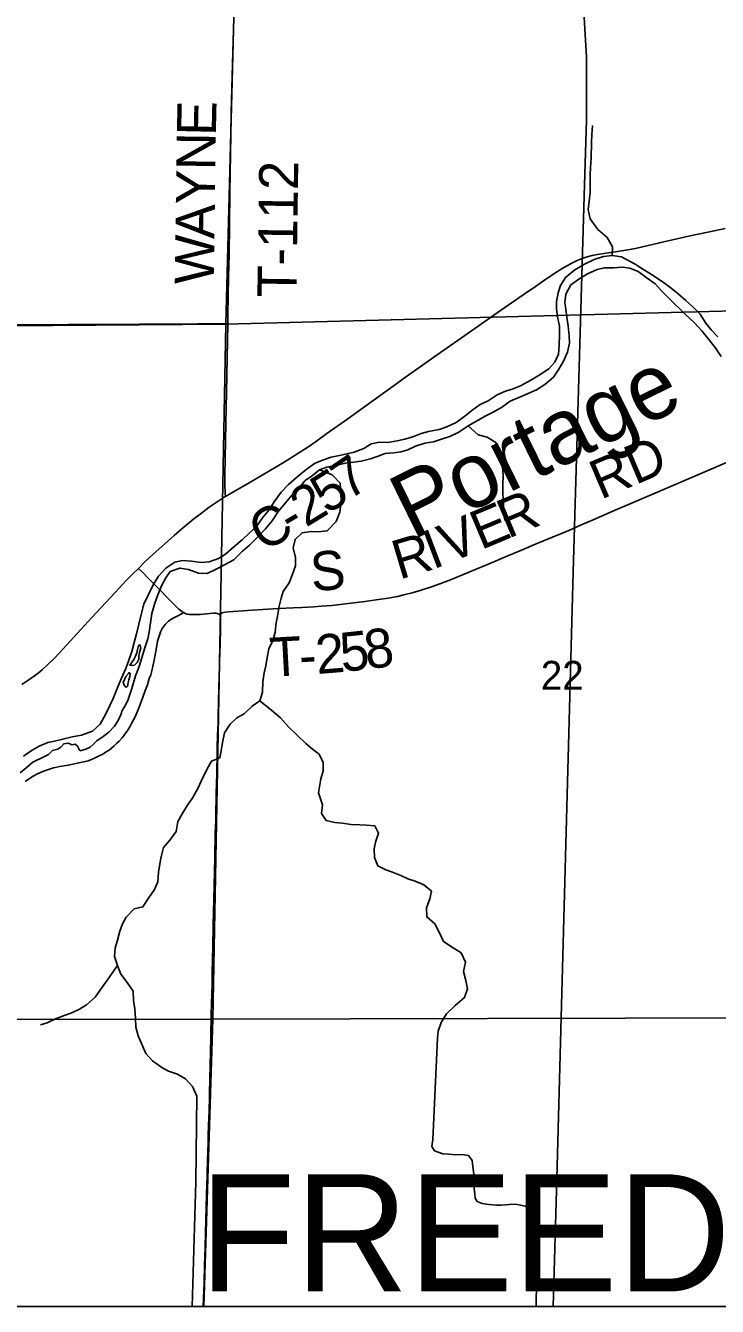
# Model space of a CAD drawing. Extents: x 0 to 34, y 0 to 22.
# Drawn here: x 3.748 to 4.754, y 14.1 to 15.963 of the extents above; entities that cross this region are included whole.
import ezdxf

# ---------------------------------------------------------------- set-up
doc = ezdxf.new("R2010")
doc.units = 0
for name, color, linetype in [('Default', 7, 'Continuous'), ('GM_X_County_Road', 7, 'Continuous'), ('GM_X_County_Road_Text', 7, 'Continuous'), ('GM_X_Major_River', 7, 'Continuous'), ('GM_X_Major_River_Text', 7, 'Continuous'), ('GM_X_Minor_River', 7, 'Continuous'), ('GM_X_Rail_Line', 7, 'Continuous'), ('GM_X_Section', 7, 'Continuous'), ('GM_X_Section_Text', 7, 'Continuous'), ('GM_X_Township_Road', 7, 'Continuous'), ('GM_X_Township_Road_Text', 7, 'Continuous'), ('GM_X_Township_Text', 7, 'Continuous'), ('SH_Cut_Line', 7, 'Continuous'), ('SH_Data', 7, 'Continuous')]:
    doc.layers.add(name, color=color, linetype=linetype)

msp = doc.modelspace()

# ---------------------------------------------------------------- linework, layer by layer
at = {"layer": 'Default'}
for points in [[(3.005, 14.1), (4.0075, 14.1), (4.0206, 14.5179), (3.0117, 14.5162)], [(4.0075, 14.1), (5.0106, 14.1), (5.0199, 14.516), (5.0199, 14.5201), (4.0206, 14.5179)]]:
    msp.add_lwpolyline(points, close=True, dxfattribs=at)
msp.add_lwpolyline([(2.1, 14.1), (7.0155, 14.1)], dxfattribs=at)
at = {"layer": 'GM_X_County_Road'}
for points in [[(4.0391, 15.2781), (4.0503, 15.2849), (4.0732, 15.298), (4.1029, 15.3151), (4.1242, 15.328), (4.144, 15.3403), (4.1571, 15.3488), (4.1712, 15.3585), (4.1863, 15.3694), (4.2167, 15.3911), (4.2395, 15.4072), (4.2862, 15.4409), (4.2975, 15.4491), (4.3418, 15.4806), (4.4018, 15.5224), (4.4387, 15.5483), (4.4514, 15.5573), (4.4732, 15.5721), (4.4899, 15.5836), (4.5014, 15.5916), (4.5181, 15.6029), (4.5272, 15.6088), (4.5352, 15.6135), (4.5434, 15.6179), (4.5504, 15.6211), (4.5576, 15.6239), (4.5649, 15.6264), (4.5724, 15.6284), (4.5799, 15.6301), (4.5891, 15.6316), (4.606, 15.6337), (4.6122, 15.6346), (4.6214, 15.6361), (4.6352, 15.6389), (4.67, 15.6471), (4.7125, 15.6564), (4.7429, 15.663), (4.7657, 15.668)], [(3.9122, 15.1734), (3.9216, 15.183), (3.933, 15.1935), (3.9644, 15.2213), (3.9761, 15.2315), (3.9929, 15.2453), (4.0039, 15.2539), (4.0151, 15.2622), (4.0253, 15.2693), (4.0371, 15.2769), (4.0391, 15.2781)], [(3.7427, 15.0044), (3.7516, 15.0102), (3.7612, 15.017), (3.7665, 15.0212), (3.7722, 15.0259), (3.7804, 15.0335), (3.7902, 15.043), (3.803, 15.0565), (3.8285, 15.0846), (3.8446, 15.1019), (3.8649, 15.1238), (3.8785, 15.1383), (3.8946, 15.1556), (3.9041, 15.1655), (3.9122, 15.1734)], [(3.9781, 15.109), (3.9775, 15.1093), (3.9748, 15.111), (3.9712, 15.1141), (3.9634, 15.1217), (3.9568, 15.1283), (3.9396, 15.146), (3.9363, 15.1493), (3.9319, 15.1536), (3.9287, 15.1569), (3.9243, 15.1612), (3.9189, 15.1667), (3.9122, 15.1734)], [(4.0306, 15.106), (4.0289, 15.1075), (4.0264, 15.108), (4.025, 15.1082), (4.022, 15.1083), (4.0159, 15.1079), (4.0021, 15.1065), (3.9959, 15.1061), (3.9896, 15.1061), (3.9864, 15.1063), (3.9833, 15.1068), (3.9803, 15.1079), (3.9781, 15.109)], [(4.0066, 14.1), (4.0078, 14.1341), (4.0085, 14.1605), (4.0088, 14.1714), (4.0093, 14.1869), (4.0104, 14.2257), (4.0113, 14.2615), (4.0117, 14.277), (4.0121, 14.291), (4.0128, 14.3158), (4.013, 14.3221), (4.0136, 14.3407), (4.0139, 14.35), (4.0143, 14.3624), (4.0149, 14.3842), (4.0154, 14.4044), (4.0156, 14.4106), (4.0161, 14.4308), (4.0169, 14.4696), (4.0174, 14.4914), (4.0182, 14.5256), (4.0193, 14.5691), (4.0196, 14.5831), (4.0201, 14.6064), (4.0204, 14.6219), (4.0211, 14.6546), (4.0219, 14.6919), (4.0232, 14.7525), (4.0241, 14.7882), (4.0246, 14.8069), (4.0248, 14.8146), (4.025, 14.8255), (4.0251, 14.8317), (4.0255, 14.8457), (4.0262, 14.8752), (4.0268, 14.9063), (4.0269, 14.9125), (4.0274, 14.9311), (4.028, 14.9482), (4.0283, 14.9591), (4.0288, 14.9793), (4.0294, 14.9995), (4.0298, 15.0166), (4.0301, 15.0305), (4.0303, 15.0399), (4.0305, 15.0492), (4.031, 15.0649), (4.0315, 15.0825), (4.0315, 15.0892), (4.0315, 15.1012), (4.0313, 15.1039), (4.0306, 15.106)]]:
    msp.add_lwpolyline(points, dxfattribs=at)
at = {"layer": 'GM_X_Major_River'}
for p, q in [((3.9126, 15.0412), (3.9127, 15.045)), ((3.8938, 15.0159), (3.891, 15.0095))]:
    msp.add_line(p, q, dxfattribs=at)
for points in [[(4.5612, 15.6161), (4.5469, 15.6077), (4.5334, 15.5966), (4.5263, 15.5847), (4.5226, 15.5741), (4.5204, 15.5609), (4.5202, 15.5514), (4.5218, 15.5392), (4.5245, 15.5255), (4.5249, 15.5126), (4.5242, 15.4982), (4.5231, 15.4849), (4.5179, 15.4733), (4.5093, 15.4636), (4.4966, 15.4552), (4.4839, 15.4476), (4.4678, 15.4388), (4.4559, 15.4342), (4.4464, 15.431), (4.4341, 15.4256), (4.421, 15.4172), (4.4095, 15.4118), (4.3991, 15.4044), (4.3868, 15.3949), (4.3744, 15.3857), (4.361, 15.3792), (4.3496, 15.3753), (4.3343, 15.3726), (4.3233, 15.3698), (4.3114, 15.3648), (4.2996, 15.3613), (4.2886, 15.3589), (4.2749, 15.3566), (4.2628, 15.3569), (4.251, 15.3545), (4.2402, 15.3479), (4.226, 15.3422), (4.2047, 15.3374), (4.1925, 15.3351), (4.1799, 15.3308), (4.1685, 15.3261), (4.1557, 15.3166), (4.1422, 15.3055), (4.1306, 15.2956), (4.1197, 15.2841), (4.1095, 15.2703), (4.1024, 15.2587), (4.0927, 15.2468), (4.084, 15.2341), (4.0739, 15.2252), (4.0631, 15.2148), (4.0511, 15.2049), (4.0387, 15.1942), (4.0287, 15.188), (4.0153, 15.183), (4.004, 15.1821), (3.9896, 15.184), (3.9764, 15.1847), (3.9653, 15.1823), (3.9522, 15.1735), (3.9414, 15.162), (3.9335, 15.1493), (3.9263, 15.1343), (3.9203, 15.1215), (3.9161, 15.1061), (3.9093, 15.0784), (3.9062, 15.0655), (3.9027, 15.0525), (3.8978, 15.0382), (3.8937, 15.0277), (3.8873, 15.0126), (3.8813, 14.9987), (3.8756, 14.9841), (3.8708, 14.9739), (3.8644, 14.9608), (3.8565, 14.947), (3.8453, 14.9366), (3.8296, 14.9309), (3.8159, 14.9282), (3.8022, 14.9251), (3.79, 14.922), (3.7805, 14.9203), (3.7679, 14.9149), (3.7575, 14.9091), (3.7451, 14.9003)], [(3.9025, 14.9986), (3.9082, 15.0171), (3.9131, 15.0306), (3.9172, 15.0434), (3.9213, 15.0566), (3.9258, 15.0709), (3.928, 15.0807), (3.9317, 15.108), (3.9362, 15.1226), (3.9407, 15.1347), (3.9459, 15.1478), (3.9523, 15.1598), (3.9585, 15.1688), (3.9727, 15.1738), (3.9851, 15.1716), (3.9998, 15.1663), (4.0123, 15.166), (4.0245, 15.1717), (4.0376, 15.1786), (4.051, 15.1859), (4.0638, 15.1985), (4.0739, 15.2074), (4.0863, 15.22), (4.0972, 15.2307), (4.1069, 15.2426), (4.116, 15.2564), (4.1261, 15.2687), (4.1357, 15.2806), (4.1456, 15.2903), (4.1546, 15.3011), (4.1654, 15.3084), (4.1758, 15.3169), (4.1861, 15.3208), (4.1991, 15.3231), (4.2135, 15.3266), (4.2253, 15.3278), (4.2363, 15.3291), (4.25, 15.3325), (4.2611, 15.3368), (4.2711, 15.3404), (4.2836, 15.3416), (4.2938, 15.3429), (4.3042, 15.346), (4.3153, 15.3514), (4.329, 15.3557), (4.3416, 15.3576), (4.353, 15.3612), (4.3652, 15.3654), (4.3783, 15.3716), (4.3921, 15.3807), (4.4175, 15.3953), (4.4274, 15.4), (4.4405, 15.4076), (4.4532, 15.4164), (4.4655, 15.4218), (4.4792, 15.4276), (4.4911, 15.433), (4.5034, 15.441), (4.5162, 15.4517), (4.5237, 15.4633), (4.5304, 15.4749), (4.5364, 15.488), (4.5394, 15.5012), (4.5389, 15.5115), (4.5373, 15.5263), (4.5354, 15.5382), (4.5338, 15.5503), (4.5325, 15.5599), (4.5339, 15.5723), (4.5411, 15.5858), (4.553, 15.5939), (4.5653, 15.6016), (4.5795, 15.6081), (4.5902, 15.6105), (4.6034, 15.6105), (4.616, 15.6114), (4.6269, 15.6099), (4.6393, 15.6051), (4.6523, 15.5957), (4.6638, 15.5874), (4.673, 15.577), (4.6841, 15.5657), (4.7085, 15.5423), (4.7208, 15.531), (4.7318, 15.519)], [(4.7551, 15.5104), (4.7455, 15.5205), (4.7378, 15.5302), (4.7294, 15.5433), (4.7196, 15.5529), (4.7087, 15.5628), (4.6972, 15.5726), (4.6845, 15.5827), (4.6726, 15.5918), (4.6585, 15.6008), (4.6447, 15.6095), (4.635, 15.6158), (4.6148, 15.6266), (4.6012, 15.6284), (4.5887, 15.6272), (4.575, 15.6226), (4.5612, 15.6161)], [(4.7318, 15.519), (4.7421, 15.5062), (4.7513, 15.4946), (4.76, 15.4815)], [(3.9127, 15.045), (3.914, 15.0511), (3.9157, 15.0579), (3.9143, 15.0621), (3.9123, 15.061), (3.9111, 15.0553), (3.9098, 15.0504), (3.9082, 15.0455), (3.9054, 15.041), (3.8995, 15.0328), (3.9029, 15.032), (3.9063, 15.0327), (3.9106, 15.0367), (3.9126, 15.0412)], [(3.891, 15.0095), (3.8902, 15.008), (3.8916, 15.0034), (3.8938, 15.0007), (3.8957, 15.0014), (3.8965, 15.0018), (3.8974, 15.0075), (3.8982, 15.0112), (3.8999, 15.0161), (3.9003, 15.0199), (3.8989, 15.0218), (3.8977, 15.0204), (3.8938, 15.0159)], [(3.74, 14.8761), (3.752, 14.8857), (3.7586, 14.8913), (3.7758, 14.8996), (3.7816, 14.9025), (3.7862, 14.9077), (3.7874, 14.9084), (3.795, 14.9105), (3.7992, 14.9134), (3.8035, 14.9183), (3.8104, 14.9192), (3.8156, 14.9168), (3.8202, 14.9175), (3.8243, 14.9143), (3.8257, 14.9105), (3.8275, 14.9082), (3.8359, 14.9103), (3.842, 14.9135), (3.8474, 14.918), (3.8517, 14.9224), (3.861, 14.929), (3.8691, 14.9353), (3.8776, 14.9438), (3.882, 14.9505), (3.886, 14.9588), (3.8888, 14.9667), (3.8932, 14.9745), (3.8971, 14.9828), (3.9025, 14.9986)]]:
    msp.add_lwpolyline(points, dxfattribs=at)
at = {"layer": 'GM_X_Minor_River'}
for points in [[(4.6012, 15.6284), (4.6019, 15.6409), (4.5939, 15.6548), (4.5806, 15.6665), (4.5692, 15.6819), (4.5665, 15.6953), (4.568, 15.7074), (4.5694, 15.7199), (4.5693, 15.7313), (4.5693, 15.7461), (4.5696, 15.7563), (4.5707, 15.7703), (4.5712, 15.7931), (4.5719, 15.8041), (4.5726, 15.8177)], [(4.3921, 15.3807), (4.4062, 15.3678), (4.4193, 15.3641), (4.432, 15.3566), (4.4363, 15.347), (4.4402, 15.3336), (4.4418, 15.3211), (4.443, 15.3089), (4.4422, 15.2949), (4.4423, 15.2816), (4.4435, 15.2683), (4.4439, 15.2557), (4.4451, 15.2432)], [(4.1758, 15.3169), (4.1942, 15.3096), (4.2056, 15.2972), (4.2068, 15.2839), (4.2072, 15.2706), (4.2053, 15.2554), (4.2001, 15.2415), (4.1869, 15.2278), (4.1736, 15.2266), (4.1637, 15.2268), (4.1504, 15.2253), (4.14, 15.2156), (4.1374, 15.2032), (4.1405, 15.1891), (4.1405, 15.1773), (4.1357, 15.1637), (4.1316, 15.1525), (4.123, 15.1398), (4.1201, 15.13), (4.1171, 15.1183), (4.1145, 15.1039), (4.1127, 15.0941), (4.1109, 15.0805), (4.1083, 15.0695), (4.1019, 15.0564), (4.0994, 15.0436), (4.0976, 15.0318), (4.095, 15.0216), (4.0932, 15.0084), (4.0928, 14.9932), (4.0887, 14.9808), (4.0779, 14.9731), (4.0659, 14.962), (4.0555, 14.9558), (4.0458, 14.9466), (4.0376, 14.9342), (4.0346, 14.9203), (4.0328, 14.9078), (4.0306, 14.8976), (4.0184, 14.8929), (4.012, 14.8817), (4.0038, 14.8648)], [(4.0887, 14.9808), (4.1064, 14.9665), (4.1188, 14.9558), (4.1306, 14.943), (4.1435, 14.9302), (4.1557, 14.9185), (4.1654, 14.9106), (4.175, 14.9032), (4.181, 14.8912), (4.1812, 14.8791), (4.1775, 14.8671)], [(4.1775, 14.8671), (4.174, 14.847), (4.1802, 14.8297), (4.1783, 14.8168), (4.1853, 14.8067), (4.1981, 14.8037), (4.2087, 14.8026), (4.2216, 14.8011), (4.2341, 14.8004), (4.244, 14.8001), (4.2561, 14.799), (4.2615, 14.7882), (4.2573, 14.7754), (4.2551, 14.7656), (4.2555, 14.753), (4.2605, 14.7407), (4.2721, 14.7347), (4.2819, 14.7314), (4.2939, 14.7268), (4.304, 14.722), (4.3146, 14.7183), (4.3273, 14.7133), (4.3385, 14.7039), (4.3359, 14.6929), (4.3313, 14.6798), (4.3317, 14.6665), (4.3436, 14.6566), (4.3504, 14.6435), (4.3561, 14.6308), (4.3699, 14.6213), (4.3818, 14.6141), (4.3879, 14.6006), (4.3849, 14.587), (4.3883, 14.574), (4.391, 14.5618), (4.3864, 14.549), (4.3728, 14.5376), (4.3603, 14.5254), (4.3527, 14.5131), (4.3482, 14.5003), (4.3475, 14.4901)], [(4.0038, 14.8648), (3.9985, 14.8532), (3.9913, 14.8401), (3.9837, 14.8289), (3.9758, 14.8166), (3.9698, 14.805), (3.9671, 14.7907), (3.958, 14.778), (3.9485, 14.7673), (3.9455, 14.7537), (3.9433, 14.7435), (3.9414, 14.7314), (3.9406, 14.7177), (3.9358, 14.7061), (3.9267, 14.6938), (3.9187, 14.6811), (3.9061, 14.6781), (3.8943, 14.6663), (3.8891, 14.6562), (3.8854, 14.6456), (3.8816, 14.6328), (3.8786, 14.6211), (3.8775, 14.609), (3.8816, 14.5956), (3.8866, 14.5833), (3.8961, 14.5709), (3.9045, 14.5585), (3.9053, 14.5451), (3.9072, 14.5329), (3.9079, 14.5189), (3.9087, 14.5059), (3.9121, 14.4933), (3.9228, 14.4679), (3.9327, 14.457), (3.9462, 14.4475), (3.9559, 14.4419), (3.969, 14.4377), (3.9806, 14.4309), (3.9909, 14.4196), (3.997, 14.4057)], [(3.8816, 14.5956), (3.8682, 14.5766), (3.8583, 14.5628), (3.8495, 14.5498), (3.8367, 14.5384), (3.8266, 14.5322), (3.8162, 14.5272), (3.802, 14.5219), (3.7916, 14.5181), (3.7793, 14.5123), (3.7697, 14.5096)], [(4.3475, 14.4901), (4.3406, 14.3429), (4.3391, 14.3323), (4.3431, 14.3261), (4.3548, 14.322), (4.3639, 14.3213), (4.3741, 14.3206), (4.3825, 14.3208), (4.3923, 14.3194), (4.3978, 14.312), (4.3987, 14.3036), (4.3999, 14.2925), (4.4001, 14.2853), (4.4008, 14.2712), (4.4017, 14.2632), (4.4023, 14.2575), (4.4052, 14.2525), (4.4124, 14.2496), (4.4218, 14.2482), (4.4332, 14.2471), (4.4397, 14.2473), (4.4519, 14.2481), (4.4614, 14.2486), (4.475, 14.2459), (4.4843, 14.2411), (4.4895, 14.236), (4.492, 14.2295), (4.4928, 14.2203), (4.4921, 14.2093), (4.4907, 14.1)], [(3.997, 14.4057), (3.9957, 14.2811), (3.9905, 14.1)]]:
    msp.add_lwpolyline(points, dxfattribs=at)
at = {"layer": 'GM_X_Rail_Line'}
msp.add_lwpolyline([(4.562, 17.1188), (4.5796, 16.883), (4.5748, 16.7925), (4.5733, 16.6553), (4.5685, 16.4905), (4.5573, 16.0706), (4.559, 15.9996), (4.5639, 15.9172), (4.5639, 15.8252), (4.5607, 15.7154), (4.5448, 15.1679), (4.5209, 14.2861), (4.5155, 14.1)], dxfattribs=at)
at = {"layer": 'GM_X_Section'}
for points in [[(3.0627, 16.5204), (4.0656, 16.5335), (4.0396, 15.5284), (3.0319, 15.521)], [(4.0656, 16.5335), (5.0695, 16.5364), (5.0389, 15.5548), (4.0396, 15.5284)], [(5.0389, 15.5548), (5.0199, 14.5201), (4.0206, 14.5179), (4.0396, 15.5284)], [(4.0396, 15.5284), (4.0206, 14.5179), (3.0117, 14.5162), (3.0319, 15.521)]]:
    msp.add_lwpolyline(points, close=True, dxfattribs=at)
at = {"layer": 'GM_X_Township_Road'}
for points in [[(4.0423, 15.5293), (4.0425, 15.5415), (4.0434, 15.5974), (4.044, 15.6301), (4.0452, 15.7203), (4.0465, 15.8042), (4.0473, 15.8369), (4.0497, 15.924), (4.051, 15.9737), (4.0528, 16.0545), (4.0549, 16.1572), (4.0567, 16.2551), (4.0575, 16.2909), (4.0583, 16.3375), (4.0594, 16.3919), (4.0599, 16.4137), (4.0603, 16.4355), (4.0608, 16.4603), (4.0612, 16.4805), (4.0616, 16.5023), (4.0623, 16.5241), (4.0624, 16.5272), (4.0626, 16.5336)], [(3.0314, 15.5164), (3.0473, 15.5163), (3.0892, 15.5169), (3.1219, 15.5176), (3.1436, 15.5179), (3.1624, 15.5182), (3.1918, 15.5189), (3.2369, 15.5198), (3.2648, 15.5204), (3.3069, 15.5211), (3.352, 15.5216), (3.4218, 15.5235), (3.5415, 15.5257), (3.582, 15.5262), (3.6333, 15.5268), (3.6908, 15.5275), (3.7545, 15.5278), (3.8105, 15.5282), (3.9131, 15.5284), (3.9567, 15.5287), (3.9987, 15.5291), (4.0375, 15.5293), (4.0423, 15.5293)], [(4.0391, 15.2781), (4.0386, 15.2825), (4.0383, 15.2858), (4.038, 15.2927), (4.0381, 15.3082), (4.0395, 15.3844), (4.0405, 15.4295), (4.0423, 15.5293)], [(4.0306, 15.106), (4.0342, 15.1085), (4.0385, 15.1096), (4.0432, 15.1102), (4.071, 15.1122), (4.1005, 15.1139), (4.116, 15.1149), (4.1377, 15.1161), (4.1501, 15.1167), (4.1672, 15.1175), (4.178, 15.1182), (4.1935, 15.1195), (4.2136, 15.1217), (4.2414, 15.1251), (4.2614, 15.1279), (4.2753, 15.1301), (4.289, 15.1326), (4.2982, 15.1347), (4.3102, 15.1378), (4.3222, 15.1413), (4.3399, 15.1471), (4.3546, 15.1524), (4.3662, 15.1568), (4.3921, 15.1673), (4.4294, 15.1829), (4.4437, 15.189), (4.4694, 15.2), (4.4909, 15.2089), (4.5382, 15.2287), (4.5554, 15.2361), (4.5739, 15.2441), (4.6024, 15.2566), (4.6352, 15.2708), (4.6752, 15.2878), (4.7396, 15.3151), (4.8265, 15.3528)], [(3.7474, 14.8635), (3.7537, 14.8678), (3.759, 14.871), (3.7643, 14.874), (3.7699, 14.8767), (3.7756, 14.879), (3.7814, 14.881), (3.7888, 14.8831), (3.7979, 14.8851), (3.8101, 14.8874), (3.8192, 14.889), (3.8299, 14.8913), (3.8329, 14.892), (3.8389, 14.8937), (3.8448, 14.8959), (3.8491, 14.8977), (3.8561, 14.9012), (3.8603, 14.9034), (3.8643, 14.9059), (3.8696, 14.9091), (3.8732, 14.9119), (3.8769, 14.9152), (3.8805, 14.9185), (3.8843, 14.9223), (3.8885, 14.9268), (3.8917, 14.9309), (3.8954, 14.936), (3.8995, 14.9428), (3.9033, 14.9496), (3.9068, 14.9566), (3.9112, 14.9665), (3.9162, 14.9792), (3.9214, 14.9942), (3.9254, 15.0042), (3.9281, 15.013), (3.9301, 15.0188), (3.932, 15.0263), (3.9351, 15.04), (3.938, 15.0553), (3.9402, 15.0674), (3.9417, 15.0734), (3.9432, 15.0778), (3.9449, 15.082), (3.947, 15.0861), (3.9495, 15.0899), (3.9514, 15.0922), (3.9535, 15.0944), (3.9558, 15.0964), (3.9595, 15.099), (3.9635, 15.1014), (3.9703, 15.1049), (3.9781, 15.109)], [(3.9781, 15.109), (3.9803, 15.1079), (3.9833, 15.1068), (3.9864, 15.1063), (3.9896, 15.1061), (3.9959, 15.1061), (4.0021, 15.1065), (4.0159, 15.1079), (4.022, 15.1083), (4.025, 15.1082), (4.0264, 15.108), (4.0289, 15.1075), (4.0306, 15.106)]]:
    msp.add_lwpolyline(points, dxfattribs=at)
at = {"layer": 'SH_Cut_Line'}
msp.add_lwpolyline([(2.1, 20.9), (2.1, 14.1), (7.0155, 14.1)], dxfattribs=at)
at = {"layer": 'SH_Data'}
msp.add_line((2.1, 14.1), (8.9, 14.1), dxfattribs=at)

# ---------------------------------------------------------------- texts
at = {"layer": 'GM_X_County_Road_Text'}
for s, rotation, p in [('7', 34.4263, (4.2179, 15.2713)), ('5', 32.5265, (4.1867, 15.2513)), ('2', 31.3922, (4.1558, 15.2324)), ('C', 30.5059, (4.0947, 15.1963)), ('-', 30.7328, (4.1351, 15.2201))]:
    msp.add_text(s, height=0.0568, rotation=rotation, dxfattribs=at).set_placement(p)
at = {"layer": 'GM_X_Major_River_Text'}
msp.add_text('Portage', height=0.09475, rotation=26.2292, dxfattribs=at).set_placement((4.3105, 15.2138))
at = {"layer": 'GM_X_Section_Text'}
msp.add_text('22', height=0.04186, rotation=0, dxfattribs=at).set_placement((4.4976, 14.997))
at = {"layer": 'GM_X_Township_Road_Text'}
for s, height, rotation, p in [('E', 0.0568, 88.6628, (4.0248, 15.8021)), ('N', 0.0568, 89.2168, (4.0241, 15.7523)), ('T-112', 0.05682, 89.175, (4.142, 15.5672)), ('Y', 0.0568, 89.2313, (4.0234, 15.7023)), ('A', 0.0568, 89.235, (4.0228, 15.6523)), ('W', 0.0568, 89.2336, (4.0219, 15.5865)), ('RD', 0.05682, 23.0637, (4.5846, 15.273)), ('R', 0.0568, 22.8238, (4.4497, 15.2162)), ('E', 0.0568, 22.825, (4.4105, 15.1997)), ('V', 0.0568, 22.4398, (4.3639, 15.1804)), ('R', 0.0568, 16.6413, (4.2916, 15.1568)), ('I', 0.0568, 20.6972, (4.3404, 15.1715)), ('S', 0.0568, 4.9763, (4.1649, 15.1398)), ('T', 0.0568, 3.1344, (4.1046, 15.0157)), ('2', 0.0568, 4.7423, (4.1721, 15.0196)), ('5', 0.0568, 6.0926, (4.2084, 15.0226)), ('8', 0.0568, 7.3117, (4.2445, 15.0265)), ('-', 0.0568, 3.5978, (4.1475, 15.018))]:
    msp.add_text(s, height=height, rotation=rotation, dxfattribs=at).set_placement(p)
at = {"layer": 'GM_X_Township_Text'}
msp.add_text('FREEDOM', height=0.17045, rotation=0, dxfattribs=at).set_placement((4.0011, 14.1217))

doc.saveas('drawing.dxf')
